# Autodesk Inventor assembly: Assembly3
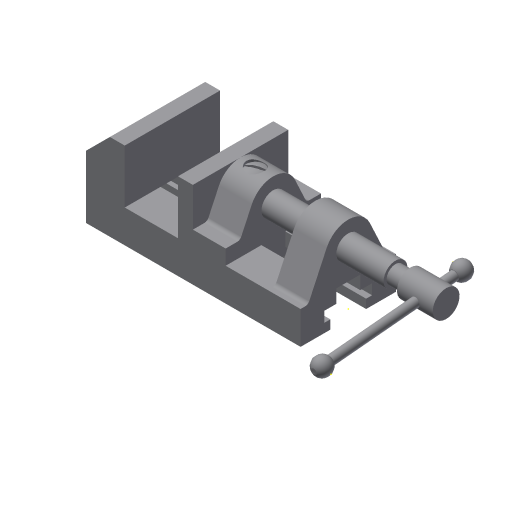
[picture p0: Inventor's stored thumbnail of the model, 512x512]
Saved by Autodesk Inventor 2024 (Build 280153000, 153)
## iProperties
Created: 2016-05
Part Number: Assembly3
Document SubType Name: Assembly
Designer: Sandeep
Author: Sandeep
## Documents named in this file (11)
- D:\PROJECTS\Project 2023\RESOURCES INVENTOR 2024\RESOURCES INVENTOR 2024\Inventor_2024_tut\Inventor_2024_tut\c09_Inv_2024_tut\c09_Inv_2024_tut\c09_Inv_tut_2024\c09_tut04_inv\Bench vice assembly.iam
- D:\PROJECTS\Project 2023\RESOURCES INVENTOR 2024\RESOURCES INVENTOR 2024\Inventor_2024_tut\Inventor_2024_tut\c09_Inv_2024_tut\c09_Inv_2024_tut\c09_Inv_tut_2024\c09_tut04_inv\Base1.ipt
- D:\PROJECTS\Project 2023\RESOURCES INVENTOR 2024\RESOURCES INVENTOR 2024\Inventor_2024_tut\Inventor_2024_tut\c09_Inv_2024_tut\c09_Inv_2024_tut\c09_Inv_tut_2024\c09_tut04_inv\base plate.ipt
- D:\PROJECTS\Project 2023\RESOURCES INVENTOR 2024\RESOURCES INVENTOR 2024\Inventor_2024_tut\Inventor_2024_tut\c09_Inv_2024_tut\c09_Inv_2024_tut\c09_Inv_tut_2024\c09_tut04_inv\vice jaw.ipt
- D:\PROJECTS\Project 2023\RESOURCES INVENTOR 2024\RESOURCES INVENTOR 2024\Inventor_2024_tut\Inventor_2024_tut\c09_Inv_2024_tut\c09_Inv_2024_tut\c09_Inv_tut_2024\c09_tut04_inv\jaw screw.ipt
- D:\PROJECTS\Project 2023\RESOURCES INVENTOR 2024\RESOURCES INVENTOR 2024\Inventor_2024_tut\Inventor_2024_tut\c09_Inv_2024_tut\c09_Inv_2024_tut\c09_Inv_tut_2024\c09_tut04_inv\clamping plate.ipt
- D:\PROJECTS\Project 2023\RESOURCES INVENTOR 2024\RESOURCES INVENTOR 2024\Inventor_2024_tut\Inventor_2024_tut\c09_Inv_2024_tut\c09_Inv_2024_tut\c09_Inv_tut_2024\c09_tut04_inv\Screw Bar.ipt
- D:\PROJECTS\Project 2023\RESOURCES INVENTOR 2024\RESOURCES INVENTOR 2024\Inventor_2024_tut\Inventor_2024_tut\c09_Inv_2024_tut\c09_Inv_2024_tut\c09_Inv_tut_2024\c09_tut04_inv\bar globes.ipt
- D:\PROJECTS\Project 2023\RESOURCES INVENTOR 2024\RESOURCES INVENTOR 2024\Inventor_2024_tut\Inventor_2024_tut\c09_Inv_2024_tut\c09_Inv_2024_tut\c09_Inv_tut_2024\c09_tut04_inv\set scew 1.ipt
- D:\PROJECTS\Project 2023\RESOURCES INVENTOR 2024\RESOURCES INVENTOR 2024\Inventor_2024_tut\Inventor_2024_tut\c09_Inv_2024_tut\c09_Inv_2024_tut\c09_Inv_tut_2024\c09_tut04_inv\set scew 2.ipt
- D:\PROJECTS\Project 2023\RESOURCES INVENTOR 2024\RESOURCES INVENTOR 2024\Inventor_2024_tut\Inventor_2024_tut\c09_Inv_2024_tut\c09_Inv_2024_tut\c09_Inv_tut_2024\c09_tut04_inv\Oval Filister.ipt
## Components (16 placed, 10 different names)
1. Base1:1
2. base plate:1 — Insert:10, Mate:15, Mate:20, Mate:22
3. base plate:2 — Mate:16, Mate:17, Mate:18, Mate:24, Mate:25, Mate:26
4. vice jaw:1 — Slider:1, Mate:1, Insert:9, Mate:2, Mate:12, Mate:13, Mate:14
5. jaw screw:1 — Cylindrical:1, Mate:1, Cylindrical:2
6. clamping plate:1 — Insert:9, Mate:2, Mate:27, Mate:28, Mate:29, Mate:30
7. Screw Bar:1 — Cylindrical:2, Rigid:2, Rigid:3
8. bar globes:1 — Rigid:2
9. bar globes:2 — Rigid:3
10. Oval Filister:1 — Mate:12, Mate:13, Mate:14
11. set scew 1:1 — Mate:19, Mate:20
12. set scew 1:2 — Mate:21, Mate:22
13. set scew 1:3 — Mate:23, Mate:24
14. set scew 1:4 — Mate:25, Mate:26
15. set scew 2:1 — Mate:27, Mate:28
16. set scew 2:2 — Mate:29, Mate:30
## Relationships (28: Mate 21, CylindricalJoint 2, WeldJoint 2, Insert 2, TranslationJoint 1)
- Slider:1 [TranslationJoint]: vice jaw:1
- Cylindrical:1: jaw screw:1
- Mate:1: vice jaw:1 ↔ jaw screw:1
- Cylindrical:2: jaw screw:1 ↔ Screw Bar:1
- Rigid:2 [WeldJoint]: Screw Bar:1 ↔ bar globes:1
- Rigid:3 [WeldJoint]: Screw Bar:1 ↔ bar globes:2
- Insert:9: vice jaw:1 ↔ clamping plate:1
- Mate:2: vice jaw:1 ↔ clamping plate:1
- Mate:12: vice jaw:1 ↔ Oval Filister:1
- Mate:13: vice jaw:1 ↔ Oval Filister:1
- Mate:14: vice jaw:1 ↔ Oval Filister:1
- Insert:10: base plate:1
- Mate:15: base plate:1
- Mate:16: base plate:2
- Mate:17: base plate:2
- Mate:18: base plate:2
- Mate:19: set scew 1:1
- Mate:20: base plate:1 ↔ set scew 1:1
- Mate:21: set scew 1:2
- Mate:22: base plate:1 ↔ set scew 1:2
- Mate:23: set scew 1:3
- Mate:24: base plate:2 ↔ set scew 1:3
- Mate:25: base plate:2 ↔ set scew 1:4
- Mate:26: base plate:2 ↔ set scew 1:4
- Mate:27: clamping plate:1 ↔ set scew 2:1
- Mate:28: clamping plate:1 ↔ set scew 2:1
- Mate:29: clamping plate:1 ↔ set scew 2:2
- Mate:30: clamping plate:1 ↔ set scew 2:2
